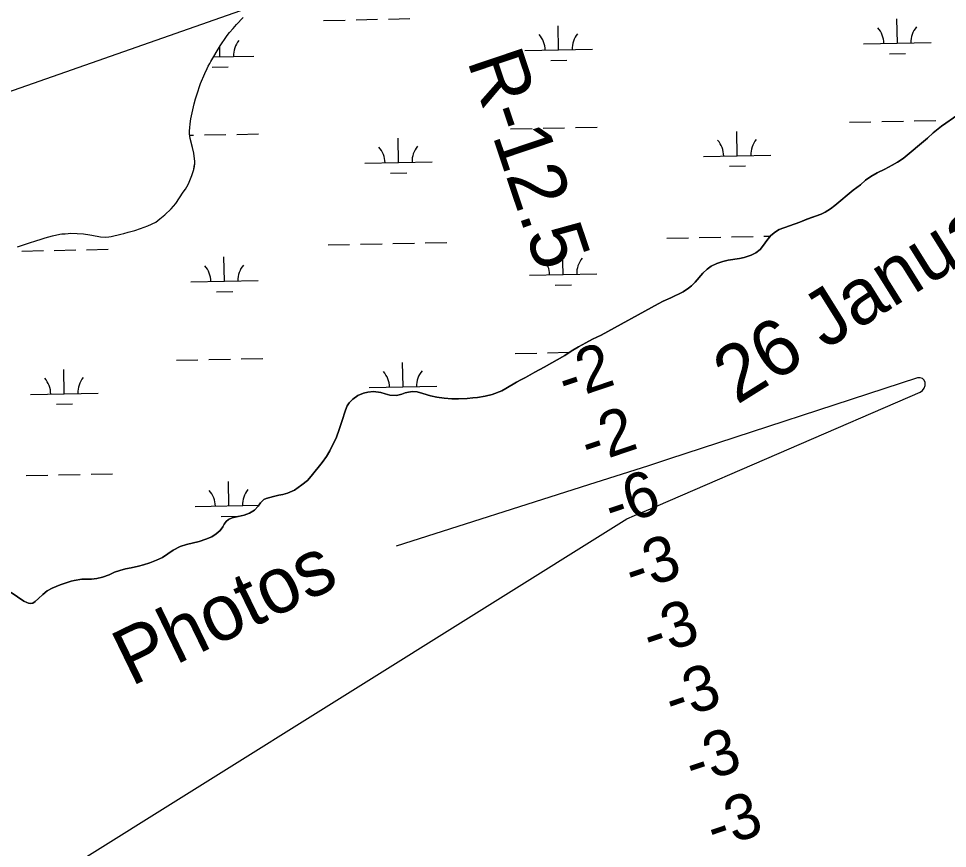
# Model space of a CAD drawing. Extents: x 3989314 to 4027622, y 243956 to 270014.
# Drawn here: x 4007210 to 4008587, y 259771 to 261000 of the extents above; entities that cross this region are included whole.
import ezdxf

# ---------------------------------------------------------------- set-up
doc = ezdxf.new("R2010")
doc.units = 0
for name, color, linetype in [('V-RIVR-EDGE', 7, 'Continuous'), ('V-RIVR-IDEN', 7, 'Continuous'), ('V-RIVR-RANG', 7, 'Continuous'), ('V-RIVR-RANG-IDEN', 7, 'Continuous'), ('V-TOPO-MINR', 7, 'Continuous'), ('V-UTIL-LINE', 7, 'Continuous'), ('V-WETL-SWMP', 7, 'Continuous')]:
    doc.layers.add(name, color=color, linetype=linetype)

msp = doc.modelspace()

# ---------------------------------------------------------------- linework, layer by layer
at = {"layer": 'V-RIVR-EDGE'}
for points in [[(4007208.8, 260662.3), (4007216.4, 260664.5), (4007229.4, 260668.8), (4007233.2, 260670.2), (4007246.9, 260674.5), (4007250, 260675.5), (4007260.9, 260678.5), (4007271.4, 260680.9), (4007274.4, 260681.4), (4007279.7, 260681.3), (4007284.2, 260682), (4007288.1, 260682.1), (4007297.2, 260682), (4007306.5, 260681.4), (4007316.1, 260680), (4007319, 260679.3), (4007331.7, 260677.1), (4007340, 260676.6), (4007344.3, 260677), (4007347.6, 260677.5), (4007362.1, 260680.7), (4007366.6, 260682), (4007372.9, 260683.6), (4007382.9, 260686.3), (4007391, 260689), (4007402.2, 260693), (4007414, 260698.8), (4007420, 260703.4), (4007427.3, 260709.3), (4007436.4, 260718.2), (4007443.6, 260726.1), (4007454.4, 260743), (4007457.7, 260747.6), (4007459.8, 260751), (4007462.2, 260755.4), (4007467, 260767.8), (4007469.9, 260776.7), (4007470.9, 260781.1), (4007471.5, 260785.4), (4007471.5, 260789.2), (4007471.2, 260792.3), (4007470, 260800.9), (4007468.1, 260809.4), (4007464.8, 260822.8), (4007463.9, 260829.6), (4007463.8, 260833.7), (4007464, 260838.5), (4007464.5, 260844.3), (4007465.7, 260851.8), (4007467.8, 260860.5), (4007470.8, 260874.1), (4007472.6, 260881.2), (4007474.4, 260887.2), (4007480.1, 260904.1), (4007486.2, 260919), (4007489.9, 260926.5), (4007491.3, 260929.5), (4007493.7, 260933.8), (4007495.2, 260936.7), (4007509.2, 260960), (4007518.4, 260973.5), (4007521.2, 260977), (4007523.2, 260979.7), (4007528.3, 260985.5), (4007533.3, 260991.6), (4007543.1, 261002)], [(4007809.5, 260444.7), (4007820.6, 260441.4), (4007830.1, 260439.3), (4007841.1, 260437.7), (4007852.3, 260436.9), (4007862, 260436.8), (4007875.2, 260437.4), (4007883.4, 260438.5), (4007890.6, 260438.8), (4007901.7, 260440.9), (4007912, 260443.2), (4007926.4, 260448.8), (4007932.6, 260452.2), (4007948.2, 260461.7), (4007954.6, 260465.2), (4007961.5, 260468.7), (4007968.6, 260472.7), (4007975.3, 260476.2), (4007989.3, 260484), (4008019.7, 260501.3), (4008029.3, 260507.7), (4008039.9, 260514), (4008050.8, 260520.1), (4008060.7, 260525.1), (4008073.5, 260531.1), (4008157.9, 260577.6), (4008165.3, 260581.5), (4008176.6, 260586.4), (4008195, 260595.4), (4008203.2, 260600.7), (4008207.3, 260604.3), (4008212.9, 260609.9), (4008224.1, 260622.9), (4008230.5, 260629), (4008236.8, 260633.4), (4008244.9, 260637.4), (4008254, 260640.4), (4008261.8, 260642.5), (4008278.4, 260644.9), (4008285.6, 260646.4), (4008295.7, 260649.6), (4008302.9, 260653), (4008309.2, 260657.9), (4008314.2, 260664.5), (4008318.9, 260671.3), (4008325.1, 260678.8), (4008332, 260684.5), (4008337.3, 260687.9), (4008368, 260698.8), (4008378.6, 260703), (4008399.3, 260710.4), (4008405.3, 260713.3), (4008413.3, 260718.3), (4008419.9, 260723.2), (4008446.9, 260745.9), (4008457.9, 260754.1), (4008465.4, 260760.6), (4008472.9, 260766.3), (4008482.3, 260771.6), (4008493.9, 260777.1), (4008504.7, 260782.9), (4008512.6, 260787.3), (4008521, 260792.9), (4008556.9, 260823.3), (4008565.6, 260831), (4008578, 260840.6), (4008601.9, 260857.8)], [(4007199.3, 260150.2), (4007218.1, 260137.3), (4007222.6, 260135.2), (4007225.4, 260134.3), (4007228.7, 260133.6), (4007231.5, 260134.2), (4007235, 260136.8), (4007240.2, 260141), (4007246.2, 260147), (4007253, 260152.6), (4007260.3, 260156.6), (4007272.1, 260161.4), (4007288.5, 260166.7), (4007293, 260168), (4007304.2, 260169.7), (4007311.6, 260169.6), (4007318.5, 260169.8), (4007326.4, 260170.6), (4007334.7, 260172.7), (4007344.6, 260176.4), (4007352.7, 260179.9), (4007360.4, 260182.7), (4007369.1, 260185), (4007377.1, 260186.8), (4007388, 260188.9), (4007395.8, 260191.1), (4007404.8, 260193.9), (4007414.7, 260197.8), (4007423.5, 260201.9), (4007439.3, 260212.5), (4007449.9, 260218), (4007459.2, 260220.9), (4007478, 260225.7), (4007488, 260228.8), (4007496.6, 260232.7), (4007503.3, 260237), (4007509.2, 260242.1), (4007513.2, 260247.4), (4007515.3, 260251.4), (4007518.2, 260255.3), (4007521.7, 260258.3), (4007527.1, 260260.7), (4007544.7, 260264.8), (4007552.6, 260267.3), (4007559.9, 260271.9), (4007565.6, 260277.9), (4007569, 260282.9), (4007574, 260287.7), (4007577.5, 260289.2), (4007588.1, 260292.3), (4007595.9, 260294.3), (4007601.8, 260295.3), (4007609, 260297), (4007619.4, 260301.7), (4007630.2, 260309.3), (4007638.4, 260315.9), (4007644.2, 260322.2), (4007660.5, 260342.4), (4007666.9, 260351.4), (4007671.6, 260360.1), (4007681.4, 260380.1), (4007685.3, 260391.3), (4007689.2, 260403.5), (4007691.4, 260409.5), (4007692.7, 260414.3), (4007694.6, 260420.3), (4007697.2, 260426.4), (4007700.5, 260431.2), (4007705.6, 260436.5), (4007713.1, 260441.9), (4007721.3, 260445.3), (4007728.1, 260447), (4007736.5, 260447.8), (4007747.2, 260446.5), (4007753.4, 260444.4), (4007760.5, 260442.3), (4007770.2, 260441.8), (4007778.4, 260443.7), (4007783.2, 260445.9), (4007788.1, 260447), (4007794.2, 260447.9), (4007801.2, 260447.2), (4007809.5, 260444.7)]]:
    msp.add_lwpolyline(points, dxfattribs=at)
at = {"layer": 'V-TOPO-MINR'}
msp.add_lwpolyline([(4006010.3, 258945.5), (4008111.5, 260259.1), (4008123.2, 260264), (4008134.9, 260268.9), (4008146.5, 260273.9), (4008158.1, 260278.9), (4008546.1, 260446.9), (4008549.7, 260449.5), (4008552.3, 260452.6), (4008553.5, 260456.6), (4008553.7, 260461), (4008551.9, 260464.6), (4008549.5, 260467.1), (4008546.1, 260468), (4008542.2, 260467.9), (4008173.6, 260347.6), (4008143.9, 260337.9), (4008114.2, 260328.3), (4008084.4, 260318.8), (4008054.7, 260309.3), (4007769.8, 260218.9)], dxfattribs=at)
at = {"layer": 'V-UTIL-LINE'}
msp.add_lwpolyline([(4011371.2, 261859.1), (4011335.1, 261835.4), (4010585.7, 261810.1), (4009561, 261669.6), (4009556.2, 261668.8), (4009323.1, 261637.1), (4006559.3, 260668.5), (4004279, 259872), (3996043.1, 256937.7), (3993486.8, 256012.2)], dxfattribs=at)
at = {"layer": 'V-WETL-SWMP'}
for p, q in [((4007662.4, 260997.5), (4007694.4, 260998.1)), ((4007710.4, 260998.5), (4007742.4, 260999.1)), ((4007758.3, 260999.4), (4007790.3, 261000.1)), ((4008010.6, 260953.7), (4008009.9, 260989.7)), ((4008512.4, 260963.7), (4008511.7, 260999.7)), ((4008462.4, 260962.7), (4008562.4, 260964.7)), ((4007508.8, 260943.7), (4007508.5, 260959)), ((4007960.6, 260952.7), (4008060.6, 260954.7)), ((4008500.7, 260948), (4008524.7, 260948.5)), ((4007499.2, 260943.5), (4007558.8, 260944.7)), ((4007998.9, 260938), (4008022.9, 260938.5)), ((4007497.1, 260928), (4007521.1, 260928.5)), ((4007987.5, 260837.8), (4008019.5, 260838.4)), ((4008035.5, 260838.7), (4008067.5, 260839.4)), ((4008441.3, 260846.8), (4008473.3, 260847.5)), ((4008489.3, 260847.8), (4008521.3, 260848.4)), ((4008537.3, 260848.7), (4008569.3, 260849.4)), ((4007464.2, 260827.3), (4007469.7, 260827.5)), ((4007485.7, 260827.8), (4007517.7, 260828.4)), ((4007533.7, 260828.7), (4007565.7, 260829.4)), ((4007939.5, 260836.8), (4007971.5, 260837.5)), ((4008275.2, 260797.1), (4008274.5, 260833.1)), ((4007773.4, 260787.1), (4007772.7, 260823.1)), ((4008225.2, 260796.1), (4008325.2, 260798.1)), ((4007723.4, 260786.1), (4007823.4, 260788.1)), ((4007761.7, 260771.4), (4007785.7, 260771.9)), ((4008263.5, 260781.4), (4008287.5, 260781.9)), ((4008170.8, 260674.9), (4008202.8, 260675.5)), ((4008218.8, 260675.9), (4008250.8, 260676.5)), ((4008266.8, 260676.8), (4008298.8, 260677.4)), ((4008314.8, 260677.8), (4008324.4, 260678)), ((4007669, 260664.9), (4007701, 260665.5)), ((4007717, 260665.9), (4007749, 260666.5)), ((4007765, 260666.8), (4007797, 260667.4)), ((4007813, 260667.8), (4007845, 260668.4)), ((4007215.2, 260655.8), (4007247.2, 260656.5)), ((4007263.2, 260656.8), (4007295.2, 260657.4)), ((4007311.2, 260657.8), (4007343.2, 260658.4)), ((4007515.4, 260611.1), (4007514.7, 260647.1)), ((4008017.3, 260621.1), (4008016.5, 260657.1)), ((4007967.3, 260620.1), (4008067.2, 260622.1)), ((4007465.5, 260610.1), (4007565.4, 260612.1)), ((4008005.6, 260605.4), (4008029.6, 260605.9)), ((4007503.8, 260595.4), (4007527.8, 260595.9)), ((4007444.4, 260494.2), (4007476.3, 260494.8)), ((4007492.3, 260495.2), (4007524.3, 260495.8)), ((4007540.3, 260496.1), (4007572.3, 260496.8)), ((4007946.2, 260504.2), (4007978.2, 260504.8)), ((4007994.2, 260505.2), (4008026.1, 260505.8)), ((4007780.1, 260454.5), (4007779.3, 260490.5)), ((4007278.2, 260444.5), (4007277.5, 260480.5)), ((4007730.1, 260453.5), (4007830, 260455.5)), ((4007228.3, 260443.5), (4007328.2, 260445.5)), ((4007266.6, 260428.8), (4007290.6, 260429.3)), ((4007221.8, 260323.2), (4007253.8, 260323.9)), ((4007269.8, 260324.2), (4007301.8, 260324.8)), ((4007317.8, 260325.2), (4007349.8, 260325.8)), ((4007522.1, 260278.5), (4007521.4, 260314.5)), ((4007472.1, 260277.5), (4007566.6, 260279.4)), ((4007510.4, 260262.8), (4007534.4, 260263.3))]:
    msp.add_line(p, q, dxfattribs=at)
for points in [[(4007288.1, 260682.1), (4007297.2, 260682), (4007306.5, 260681.4), (4007316.1, 260680), (4007319, 260679.3), (4007331.7, 260677.1), (4007340, 260676.6), (4007344.3, 260677), (4007347.6, 260677.5), (4007362.2, 260680.7), (4007366.6, 260682), (4007372.9, 260683.6), (4007382.9, 260686.3), (4007391, 260689), (4007402.2, 260693), (4007414, 260698.8), (4007420, 260703.4), (4007427.3, 260709.3), (4007436.4, 260718.2), (4007443.6, 260726.1), (4007454.4, 260743), (4007457.7, 260747.6), (4007459.8, 260751), (4007462.2, 260755.4), (4007467, 260767.8), (4007469.9, 260776.7), (4007470.8, 260781.1), (4007471.5, 260785.4), (4007471.5, 260789.2), (4007471.2, 260792.3), (4007470, 260800.9), (4007468.1, 260809.4), (4007464.8, 260822.8), (4007463.9, 260829.6), (4007463.8, 260833.7), (4007464, 260838.5), (4007464.5, 260844.3), (4007465.7, 260851.8), (4007467.8, 260860.5), (4007470.8, 260874.1), (4007472.6, 260881.2), (4007474.4, 260887.2), (4007480.1, 260904.1), (4007486.2, 260919), (4007489.9, 260926.5), (4007491.3, 260929.5), (4007493.7, 260933.8), (4007495.2, 260936.7), (4007509.2, 260960), (4007518.4, 260973.5), (4007521.2, 260977), (4007523.2, 260979.7), (4007528.3, 260985.5), (4007533.3, 260991.6), (4007543.1, 261002)], [(4008601.9, 260857.8), (4008578, 260840.6), (4008565.6, 260831), (4008556.9, 260823.3), (4008521, 260792.9), (4008512.6, 260787.3), (4008504.7, 260782.9), (4008493.9, 260777.1), (4008482.3, 260771.6), (4008472.9, 260766.3), (4008465.4, 260760.6), (4008457.9, 260754.1), (4008446.9, 260745.9), (4008419.9, 260723.2), (4008413.3, 260718.3), (4008405.3, 260713.3), (4008399.3, 260710.4), (4008378.5, 260703), (4008368, 260698.8), (4008337.3, 260687.9), (4008332, 260684.5), (4008325.1, 260678.8), (4008318.9, 260671.3), (4008314.2, 260664.5), (4008309.2, 260657.9), (4008302.9, 260653), (4008295.7, 260649.6), (4008285.6, 260646.4), (4008278.4, 260644.9), (4008261.8, 260642.5), (4008254, 260640.4), (4008244.9, 260637.4), (4008236.8, 260633.4), (4008230.5, 260629), (4008224.1, 260622.9), (4008212.9, 260609.9), (4008207.3, 260604.3), (4008203.2, 260600.7), (4008195, 260595.4), (4008176.6, 260586.4), (4008165.3, 260581.5), (4008157.9, 260577.6), (4008073.5, 260531.1), (4008060.7, 260525.1), (4008050.8, 260520.1), (4008039.9, 260514), (4008029.3, 260507.7), (4008019.7, 260501.3), (4007989.3, 260484), (4007975.3, 260476.2), (4007968.6, 260472.7), (4007961.5, 260468.7), (4007954.6, 260465.2), (4007948.2, 260461.7), (4007932.6, 260452.2), (4007926.4, 260448.8), (4007911.9, 260443.2), (4007901.7, 260440.9), (4007890.6, 260438.8)], [(4007208.8, 260662.3), (4007216.4, 260664.5), (4007229.4, 260668.8), (4007233.2, 260670.2), (4007246.9, 260674.5), (4007250, 260675.5), (4007260.9, 260678.5), (4007271.4, 260680.9), (4007274.4, 260681.4), (4007279.7, 260681.3), (4007284.2, 260682), (4007288.1, 260682.1)], [(4007890.6, 260438.8), (4007883.4, 260438.5), (4007875.2, 260437.4), (4007862, 260436.8), (4007852.3, 260436.9), (4007841.1, 260437.7), (4007830.1, 260439.3), (4007820.6, 260441.4), (4007809.5, 260444.7), (4007801.2, 260447.2), (4007794.2, 260447.9), (4007788.1, 260447), (4007783.2, 260445.9), (4007778.4, 260443.7), (4007770.2, 260441.8), (4007760.5, 260442.3), (4007753.4, 260444.4), (4007747.2, 260446.5), (4007736.5, 260447.8), (4007728.1, 260447), (4007721.3, 260445.3), (4007713.1, 260441.9), (4007705.6, 260436.5), (4007700.5, 260431.2), (4007697.2, 260426.4), (4007694.6, 260420.3), (4007692.7, 260414.3), (4007691.4, 260409.5), (4007689.2, 260403.5), (4007685.3, 260391.3), (4007681.4, 260380.1), (4007671.6, 260360.1), (4007666.9, 260351.4), (4007660.5, 260342.4), (4007644.2, 260322.2), (4007638.4, 260315.9), (4007630.2, 260309.3), (4007619.4, 260301.7), (4007609, 260297), (4007601.8, 260295.3), (4007595.9, 260294.3), (4007588.1, 260292.3), (4007577.5, 260289.2), (4007574, 260287.7), (4007569, 260282.9), (4007565.6, 260277.9), (4007559.9, 260271.9), (4007552.6, 260267.3), (4007544.7, 260264.8), (4007527.1, 260260.7), (4007521.7, 260258.3), (4007518.2, 260255.3), (4007515.3, 260251.4), (4007513.2, 260247.4), (4007509.2, 260242.1), (4007503.3, 260237), (4007496.6, 260232.7), (4007488, 260228.8), (4007478, 260225.7), (4007459.2, 260220.9), (4007449.9, 260218), (4007439.3, 260212.5), (4007423.5, 260201.9), (4007414.7, 260197.8), (4007404.8, 260193.9), (4007395.8, 260191.1), (4007388, 260188.9), (4007377.1, 260186.8), (4007369.1, 260185), (4007360.4, 260182.7), (4007352.7, 260179.9), (4007344.6, 260176.4), (4007334.7, 260172.7), (4007326.4, 260170.6), (4007318.5, 260169.8), (4007311.6, 260169.6), (4007304.2, 260169.7), (4007293, 260168), (4007288.5, 260166.7), (4007272.1, 260161.4), (4007260.3, 260156.6), (4007253, 260152.6), (4007246.2, 260147), (4007240.2, 260141), (4007235, 260136.8), (4007231.5, 260134.2), (4007228.7, 260133.6), (4007225.4, 260134.3), (4007222.6, 260135.2), (4007218.1, 260137.3), (4007199.3, 260150.2)]]:
    msp.add_lwpolyline(points, dxfattribs=at)
for centre, start, end in [((4007955.4, 260953.1), 0.3699, 41.9135), ((4008065.8, 260955.3), 140.3699, 181.9135), ((4008457.2, 260963.1), 0.3699, 41.9135), ((4008567.7, 260965.3), 140.3699, 181.9135), ((4007564, 260945.3), 140.3699, 181.9135), ((4007828.6, 260788.6), 140.3699, 181.9135), ((4008220, 260796.4), 0.3699, 41.9135), ((4008330.5, 260798.6), 140.3699, 181.9135), ((4007718.2, 260786.4), 0.3699, 41.9135), ((4007460.2, 260610.5), 0.3699, 41.9135), ((4007570.7, 260612.7), 140.3699, 181.9135), ((4007962, 260620.5), 0.3699, 41.9135), ((4008072.5, 260622.7), 140.3699, 181.9135), ((4007223, 260443.8), 0.3699, 41.9135), ((4007333.5, 260446), 140.3699, 181.9135), ((4007724.8, 260453.8), 0.3699, 41.9135), ((4007835.3, 260456), 140.3699, 181.9135), ((4007577.3, 260280), 140.3699, 181.9135), ((4007466.8, 260277.8), 0.3699, 41.9135)]:
    msp.add_arc(centre, 35.2, start, end, dxfattribs=at)

# ---------------------------------------------------------------- texts
at = {"layer": 'V-RIVR-IDEN'}
for s, rotation, p in [('26 January', 32.0054, (4008274.7, 260427.5)), ('Photos', 25.9065, (4007377.4, 260010.3))]:
    msp.add_text(s, height=83, rotation=rotation, dxfattribs=at).set_placement(p)
at = {"layer": 'V-RIVR-RANG'}
for s, p in [('-2', (4008021.5, 260433.4)), ('-2', (4008055.4, 260339)), ('-6', (4008090.4, 260245.2)), ('-3', (4008120.8, 260150)), ('-3', (4008147.5, 260053.7)), ('-3', (4008180, 259958.9)), ('-3', (4008210, 259863.5)), ('-3', (4008241.7, 259768.8))]:
    msp.add_text(s, height=67, rotation=18.6205, dxfattribs=at).set_placement(p)
at = {"layer": 'V-RIVR-RANG-IDEN'}
msp.add_text('R-12.5', height=83, rotation=288.6204, dxfattribs=at).set_placement((4007874.7, 260938))

doc.saveas('drawing.dxf')
